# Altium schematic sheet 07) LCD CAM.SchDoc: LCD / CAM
size A3; Origin: Eagle; DocumentNumber: 7; SheetNumber: 7; SheetTotal: 10
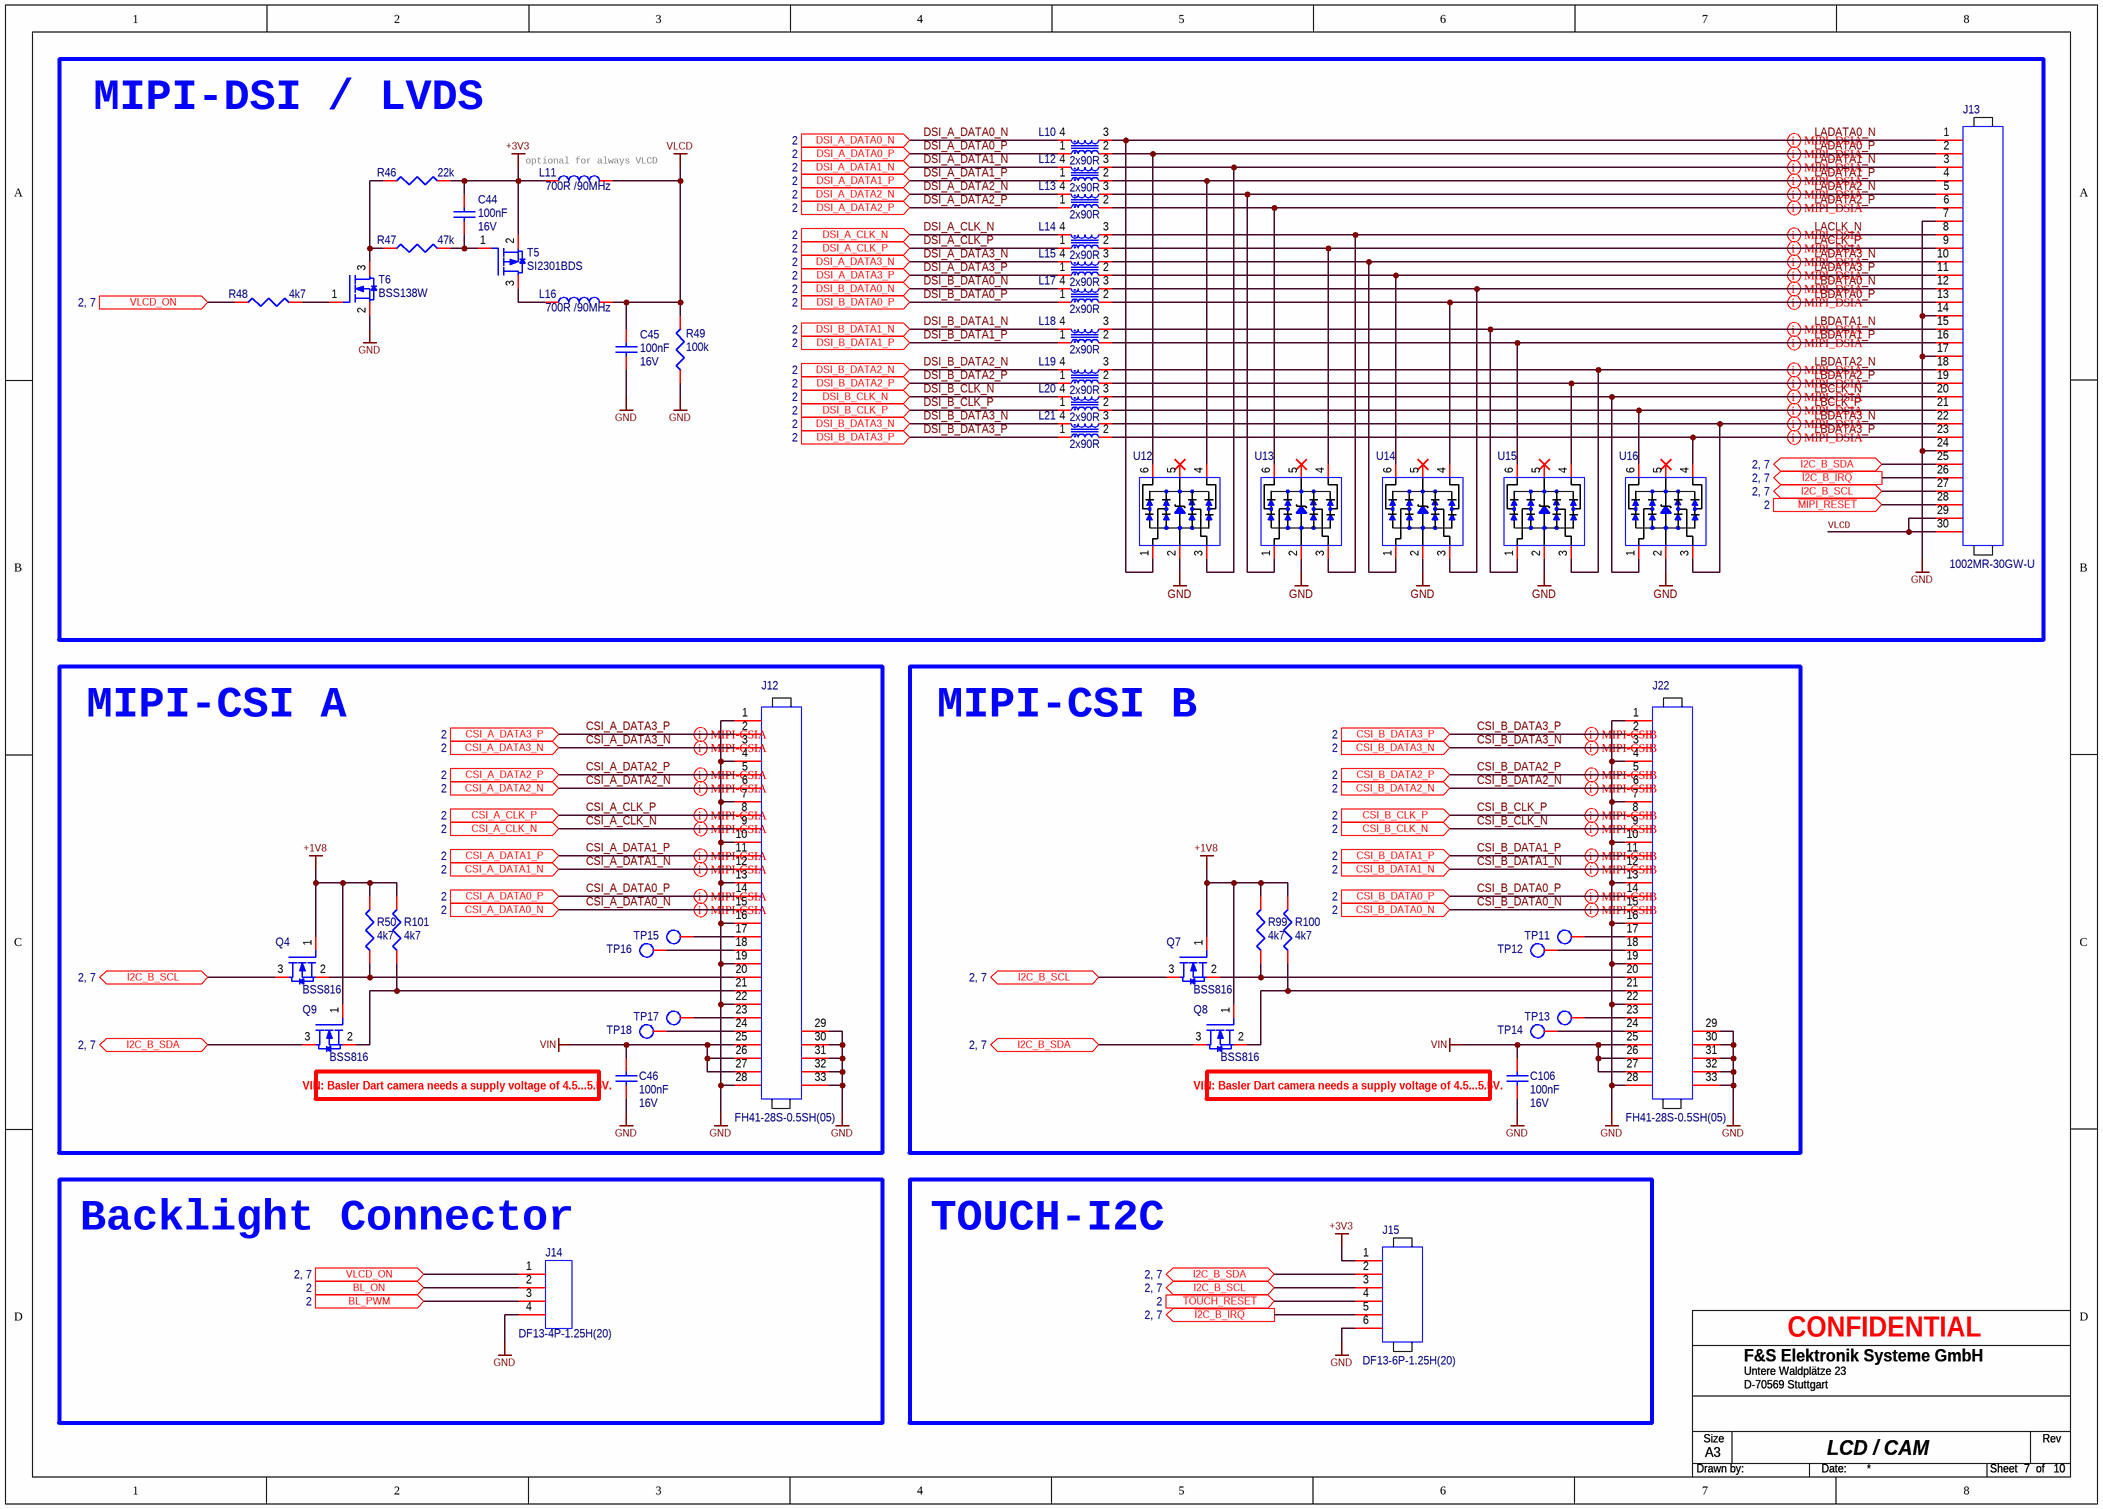
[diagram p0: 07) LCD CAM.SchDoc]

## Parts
C44  100nF  Voltage: 16V  [C0402]
C45  100nF  Voltage: 16V  [C0402]
C46  100nF  Voltage: 16V  [C0402]
C106  100nF  Voltage: 16V  [C0402]
J12  FH41-28S-0.5SH(05)  [FH41-28S-0.5SH(05)]
J13  1002MR-30GW-U  [JAE-30Pol.]
J14  DF13-4P-1.25H(20)  [DF13-4P-1.25H(20)]
J15  DF13-6P-1.25H(20)  [DF13-6P-1.25H(20)]
J22  FH41-28S-0.5SH(05)  [FH41-28S-0.5SH(05)]
L10  2x90R  [DLP11SN900HL2L]
L11  700R /90MHz  [L1206]
L12  2x90R  [DLP11SN900HL2L]
L13  2x90R  [DLP11SN900HL2L]
L14  2x90R  [DLP11SN900HL2L]
L15  2x90R  [DLP11SN900HL2L]
L16  700R /90MHz  [L1206]
L17  2x90R  [DLP11SN900HL2L]
L18  2x90R  [DLP11SN900HL2L]
L19  2x90R  [DLP11SN900HL2L]
L20  2x90R  [DLP11SN900HL2L]
L21  2x90R  [DLP11SN900HL2L]
Q4  BSS816  [SOT323 (SC70)]
Q7  BSS816  [SOT323 (SC70)]
Q8  BSS816  [SOT323 (SC70)]
Q9  BSS816  [SOT323 (SC70)]
R46  22k  [R0402]
R47  47k  [R0402]
R48  4k7  [R0402]
R49  100k  [R0402]
R50  4k7  [R0402]
R99  4k7  [R0402]
R100  4k7  [R0402]
R101  4k7  [R0402]
T5  SI2301BDS  [SOT23-3]
T6  BSS138W  [SOT323 (SC70)]
TP11  TESTPOINT  [TESTPOINT]  (value not drawn)  (mechanical)
TP12  TESTPOINT  [TESTPOINT]  (value not drawn)  (mechanical)
TP13  TESTPOINT  [TESTPOINT]  (value not drawn)  (mechanical)
TP14  TESTPOINT  [TESTPOINT]  (value not drawn)  (mechanical)
TP15  TESTPOINT  [TESTPOINT]  (value not drawn)  (mechanical)
TP16  TESTPOINT  [TESTPOINT]  (value not drawn)  (mechanical)
TP17  TESTPOINT  [TESTPOINT]  (value not drawn)  (mechanical)
TP18  TESTPOINT  [TESTPOINT]  (value not drawn)  (mechanical)
U12  TVS Diode  [SOT23-6]  (value not drawn)
U13  TVS Diode  [SOT23-6]  (value not drawn)
U14  TVS Diode  [SOT23-6]  (value not drawn)
U15  TVS Diode  [SOT23-6]  (value not drawn)
U16  TVS Diode  [SOT23-6]  (value not drawn)

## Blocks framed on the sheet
MIPI-DSI / LVDS: C44 C45 J13 L10-L21 R46-R49 T5 T6 U12-U16
MIPI-CSI A: C46 J12 Q4 Q9 R50 R101 TP15-TP18
MIPI-CSI B: C106 J22 Q7 Q8 R99 R100 TP11-TP14
Backlight Connector: J14
TOUCH-I2C: J15

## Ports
BL_ON (in, see 2), BL_PWM (in, see 2), CSI_A_CLK_N (in, see 2), CSI_A_CLK_P (in, see 2), CSI_A_DATA0_N (in, see 2), CSI_A_DATA0_P (in, see 2), CSI_A_DATA1_N (in, see 2), CSI_A_DATA1_P (in, see 2), CSI_A_DATA2_N (in, see 2), CSI_A_DATA2_P (in, see 2), CSI_A_DATA3_N (in, see 2), CSI_A_DATA3_P (in, see 2), CSI_B_CLK_N (in, see 2), CSI_B_CLK_P (in, see 2), CSI_B_DATA0_N (in, see 2), CSI_B_DATA0_P (in, see 2), CSI_B_DATA1_N (in, see 2), CSI_B_DATA1_P (in, see 2), CSI_B_DATA2_N (in, see 2), CSI_B_DATA2_P (in, see 2), CSI_B_DATA3_N (in, see 2), CSI_B_DATA3_P (in, see 2), DSI_A_CLK_N (in, see 2), DSI_A_CLK_P (in, see 2), DSI_A_DATA0_N (in, see 2), DSI_A_DATA0_P (in, see 2), DSI_A_DATA1_N (in, see 2), DSI_A_DATA1_P (in, see 2), DSI_A_DATA2_N (in, see 2), DSI_A_DATA2_P (in, see 2), DSI_A_DATA3_N (in, see 2), DSI_A_DATA3_P (in, see 2), DSI_B_CLK_N (in, see 2), DSI_B_CLK_P (in, see 2), DSI_B_DATA0_N (in, see 2), DSI_B_DATA0_P (in, see 2), DSI_B_DATA1_N (in, see 2), DSI_B_DATA1_P (in, see 2), DSI_B_DATA2_N (in, see 2), DSI_B_DATA2_P (in, see 2), DSI_B_DATA3_N (in, see 2), DSI_B_DATA3_P (in, see 2), I2C_B_SCL (bidir, see 2, 7), I2C_B_SDA (bidir, see 2, 7), VLCD_ON (in, see 2, 7), ~{I2C_B_IRQ} (out, see 2, 7), ~{MIPI_RESET} (in, see 2), ~{TOUCH_RESET} (in, see 2)

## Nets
+1V8: Q4.1 Q7.1 Q8.1 Q9.1 R50.2 R99.2 R100.2 R101.2
+3V3: C44.2 J15.1 L11.1 R46.2 T5.2
GND: C45.1 C46.1 C106.1 J12.1 J12.4 J12.7 J12.10 J12.13 J12.16 J12.19 J12.22 J12.28 J12.29 J12.30 J12.31 J12.32 J12.33 J13.7 J13.14 J13.17 J13.24 J14.4 J15.6 J22.1 J22.4 J22.7 J22.10 J22.13 J22.16 J22.19 J22.22 J22.28 J22.29 J22.30 J22.31 J22.32 J22.33 R49.1 T6.2 U12.2(GND) U13.2(GND) U14.2(GND) U15.2(GND) U16.2(GND)
VIN: C46.2 C106.2 J12.25 J12.26 J12.27 J22.25 J22.26 J22.27
VLCD: C45.2 J13.29 J13.30 L11.2 L16.2 R49.2
~{TOUCH_RESET}: J15.4 ; port ~{TOUCH_RESET}
BL_ON: J14.2 ; port BL_ON
BL_PWM: J14.3 ; port BL_PWM
CSI_A_CLK_N: J12.9 ; port CSI_A_CLK_N
CSI_A_CLK_P: J12.8 ; port CSI_A_CLK_P
CSI_A_DATA0_N: J12.15 ; port CSI_A_DATA0_N
CSI_A_DATA0_P: J12.14 ; port CSI_A_DATA0_P
CSI_A_DATA1_N: J12.12 ; port CSI_A_DATA1_N
CSI_A_DATA1_P: J12.11 ; port CSI_A_DATA1_P
CSI_A_DATA2_N: J12.6 ; port CSI_A_DATA2_N
CSI_A_DATA2_P: J12.5 ; port CSI_A_DATA2_P
CSI_A_DATA3_N: J12.3 ; port CSI_A_DATA3_N
CSI_A_DATA3_P: J12.2 ; port CSI_A_DATA3_P
CSI_B_CLK_N: J22.9 ; port CSI_B_CLK_N
CSI_B_CLK_P: J22.8 ; port CSI_B_CLK_P
CSI_B_DATA0_N: J22.15 ; port CSI_B_DATA0_N
CSI_B_DATA0_P: J22.14 ; port CSI_B_DATA0_P
CSI_B_DATA1_N: J22.12 ; port CSI_B_DATA1_N
CSI_B_DATA1_P: J22.11 ; port CSI_B_DATA1_P
CSI_B_DATA2_N: J22.6 ; port CSI_B_DATA2_N
CSI_B_DATA2_P: J22.5 ; port CSI_B_DATA2_P
CSI_B_DATA3_N: J22.3 ; port CSI_B_DATA3_N
CSI_B_DATA3_P: J22.2 ; port CSI_B_DATA3_P
DSI_A_CLK_N: L14.4 ; port DSI_A_CLK_N
DSI_A_CLK_P: L14.1 ; port DSI_A_CLK_P
DSI_A_DATA0_N: L10.4 ; port DSI_A_DATA0_N
DSI_A_DATA0_P: L10.1 ; port DSI_A_DATA0_P
DSI_A_DATA1_N: L12.4 ; port DSI_A_DATA1_N
DSI_A_DATA1_P: L12.1 ; port DSI_A_DATA1_P
DSI_A_DATA2_N: L13.4 ; port DSI_A_DATA2_N
DSI_A_DATA2_P: L13.1 ; port DSI_A_DATA2_P
DSI_A_DATA3_N: L15.4 ; port DSI_A_DATA3_N
DSI_A_DATA3_P: L15.1 ; port DSI_A_DATA3_P
DSI_B_CLK_N: L20.4 ; port DSI_B_CLK_N
DSI_B_CLK_P: L20.1 ; port DSI_B_CLK_P
DSI_B_DATA0_N: L17.4 ; port DSI_B_DATA0_N
DSI_B_DATA0_P: L17.1 ; port DSI_B_DATA0_P
DSI_B_DATA1_N: L18.4 ; port DSI_B_DATA1_N
DSI_B_DATA1_P: L18.1 ; port DSI_B_DATA1_P
DSI_B_DATA2_N: L19.4 ; port DSI_B_DATA2_N
DSI_B_DATA2_P: L19.1 ; port DSI_B_DATA2_P
DSI_B_DATA3_N: L21.4 ; port DSI_B_DATA3_N
DSI_B_DATA3_P: L21.1 ; port DSI_B_DATA3_P
I2C_B_SCL: J13.27 J15.3 Q4.3 Q7.3 ; port I2C_B_SCL
I2C_B_SDA: J13.25 J15.2 Q8.3 Q9.3 ; port I2C_B_SDA
~{I2C_B_IRQ}: J13.26 J15.5 ; port ~{I2C_B_IRQ}
LACLK_N: J13.8 L14.3 U13.3(I/O3)
LACLK_P: J13.9 L14.2 U13.4(I/O4)
LADATA0_N: J13.1 L10.3 U12.1(I/O1)
LADATA0_P: J13.2 L10.2 U12.6(I/O6)
LADATA1_N: J13.3 L12.3 U12.3(I/O3)
LADATA1_P: J13.4 L12.2 U12.4(I/O4)
LADATA2_N: J13.5 L13.3 U13.1(I/O1)
LADATA2_P: J13.6 L13.2 U13.6(I/O6)
LADATA3_N: J13.10 L15.3 U14.1(I/O1)
LADATA3_P: J13.11 L15.2 U14.6(I/O6)
LBCLK_N: J13.20 L20.3 U16.1(I/O1)
LBCLK_P: J13.21 L20.2 U16.6(I/O6)
LBDATA0_N: J13.12 L17.3 U14.3(I/O3)
LBDATA0_P: J13.13 L17.2 U14.4(I/O4)
LBDATA1_N: J13.15 L18.3 U15.1(I/O1)
LBDATA1_P: J13.16 L18.2 U15.6(I/O6)
LBDATA2_N: J13.18 L19.3 U15.3(I/O3)
LBDATA2_P: J13.19 L19.2 U15.4(I/O4)
LBDATA3_N: J13.22 L21.3 U16.3(I/O3)
LBDATA3_P: J13.23 L21.2 U16.4(I/O4)
~{MIPI_RESET}: J13.28 ; port ~{MIPI_RESET}
VLCD_ON: J14.1 R48.1 ; port VLCD_ON
NetC44_1: C44.1 R47.2 T5.1
NetJ12_17: J12.17 TP15.1(TP)
NetJ12_18: J12.18 TP16.1(TP)
NetJ12_20: J12.20 Q4.2 R50.1
NetJ12_21: J12.21 Q9.2 R101.1
NetJ12_23: J12.23 TP17.1(TP)
NetJ12_24: J12.24 TP18.1(TP)
NetJ22_17: J22.17 TP11.1(TP)
NetJ22_18: J22.18 TP12.1(TP)
NetJ22_20: J22.20 Q7.2 R99.1
NetJ22_21: J22.21 Q8.2 R100.1
NetJ22_23: J22.23 TP13.1(TP)
NetJ22_24: J22.24 TP14.1(TP)
NetL16_1: L16.1 T5.3
NetR46_1: R46.1 R47.1 T6.3
NetR48_2: R48.2 T6.1

Not connected (* = marked no-connect by the designer): U12 5(VCC)*; U13 5(VCC)*; U14 5(VCC)*; U15 5(VCC)*; U16 5(VCC)*

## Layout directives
differential pair; differential pair class MIPI-DSI: LACLK_N, LACLK_P, LADATA0_N, LADATA0_P, LADATA1_N, LADATA1_P, LADATA2_N, LADATA2_P, LADATA3_N, LADATA3_P, LBCLK_N, LBCLK_P, LBDATA0_N, LBDATA0_P, LBDATA1_N, LBDATA1_P, LBDATA2_N, LBDATA2_P, LBDATA3_N, LBDATA3_P
differential pair; differential pair class MIPI-CSI_A: CSI_A_CLK_N, CSI_A_CLK_P, CSI_A_DATA0_N, CSI_A_DATA0_P, CSI_A_DATA1_N, CSI_A_DATA1_P, CSI_A_DATA2_N, CSI_A_DATA2_P, CSI_A_DATA3_N, CSI_A_DATA3_P
differential pair; differential pair class MIPI-CSI_B: CSI_B_CLK_N, CSI_B_CLK_P, CSI_B_DATA0_N, CSI_B_DATA0_P, CSI_B_DATA1_N, CSI_B_DATA1_P, CSI_B_DATA2_N, CSI_B_DATA2_P, CSI_B_DATA3_N, CSI_B_DATA3_P

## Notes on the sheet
- (near L11) optional for always VLCD
- (near C46) VIN: Basler Dart camera needs a supply voltage of 4.5...5.5V.
- (near C106) VIN: Basler Dart camera needs a supply voltage of 4.5...5.5V.

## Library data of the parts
C44-C46 C106 = 380: 100nF  10%  16V  X7R  0402; FS-EDV-Nummer: B.CKV.42; Class: Capacitor Ceramic; Tolerance: 10; ID: 380
J12 J22 = 2781: ID: 2781; Class: Connector; FS-EDV-Nummer: B.MBU.1R28PL.2
J13 = 2728: FPC 30 pol. 1.00mm side entry SMT; FS-EDV-Nummer: B.MBU.1R30PL.3; Class: Connector; ID: 2728
J14 = 2721: Stiftl. 4 pol. crimpable  liegend RM:1.25; FS-EDV-Nummer: B.MST.1R4PL.9; Class: Connector; ID: 2721
J15 = 2720: Stiftl. 6 pol. crimpable  liegend RM:1.25; FS-EDV-Nummer: B.MST.1R6PL.2; Class: Connector; ID: 2720
L10 L12-L15 L17-L21 = 2731: Common Mode Choke  20%  2x 90 Ohm  0504; FS-EDV-Nummer: B.EMVFER.13; Voltage: 5V; Power: 150mA; ID: 2731
L11 L16 = 2705: WE-CBF  25%  700R  90MHz  EMI  1206; Part Number: 74279218; FS-EDV-Nummer: B.EMVFER.5; Class: Ferit; ID: 2705
Q4 Q7-Q9 = 2772: MOSFET N-CH 20V 1.4A SOT323(SC-70); ID: 2772; FS-EDV-Nummer: B.TPMFN.12; Power: 0,5W
R46 = 179: 22k 1/16W 1% SMD 0402; FS-EDV-Nummer: B.R22K0.1; Tolerance: 1; ID: 179
R47 = 186: 47k 1/16W 1% SMD 0402; FS-EDV-Nummer: B.R47K0.1; Tolerance: 1; ID: 186
R48 = 184: 4k7 1/16W max 5% SMD 0402; FS-EDV-Nummer: B.R4K7.3; Tolerance: 5; ID: 184
R49 = 177: 100k 1/16W 1% SMD 0402; FS-EDV-Nummer: B.R100K.3; Tolerance: 1; ID: 177
R50 R99-R101 = 184: 4k7 1/16W max 5% SMD 0402; ID: 184; FS-EDV-Nummer: B.R4K7.3; Tolerance: 5
T5 = 2691: Si2301BDS SOT-23 P-Kanal; FS-EDV-Nummer: B.TPMFP.2.S; Class: MOSFET; ID: 2691
T6 = 2689: BSS138W SOT323(SC-70) N-Kanal; FS-EDV-Nummer: B.TPMFN.10; Class: MOSFET; ID: 2689
U12-U16 = 2710: 4 Channel  5,5V  TVS Diode Array  SOT-23-6; Part Number: AOZ8904CIL; CLASS: ESD; FS-EDV-Nummer: B.EMVSUP.2; ID: 2710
